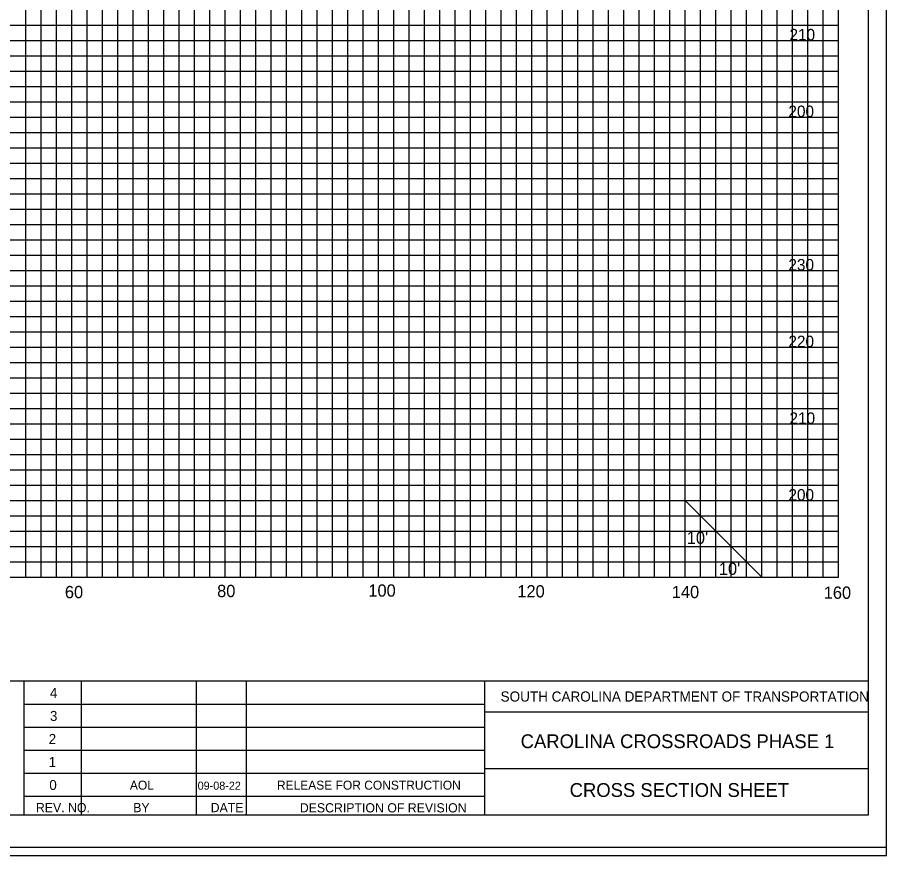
# Model space of a CAD drawing. Extents: x 967 to 1326, y 964 to 2304.
# Drawn here: x 1212.9 to 1326.3, y 963.7 to 1073 of the extents above; entities that cross this region are included whole.
import ezdxf

# ---------------------------------------------------------------- set-up
doc = ezdxf.new("R2010")
doc.units = 0
for name, color, linetype in [('Default', 7, 'Continuous'), ('RD_GPK_XS_Cell', 7, 'Continuous'), ('RD_PD_PaveShd', 7, 'Continuous'), ('RD_XS_ExGround', 7, 'Continuous'), ('RD_XS_ExPaveRet', 7, 'Continuous'), ('RD_XS_Misc_Line', 7, 'Continuous'), ('RD_XS_PaveOvlay', 7, 'Continuous'), ('RD_XS_TX_Elev_EX', 7, 'Continuous')]:
    doc.layers.add(name, color=color, linetype=linetype)

msp = doc.modelspace()

# ---------------------------------------------------------------- linework, layer by layer
at = {"layer": 'RD_GPK_XS_Cell'}
for p, q in [((1220, 1000), (1220, 1170)), ((1230, 1000), (1230, 1170)), ((1240, 1000), (1240, 1170)), ((1250, 1000), (1250, 1170)), ((1260, 1000), (1260, 1170)), ((1270, 1000), (1270, 1170)), ((1280, 1000), (1280, 1170)), ((1290, 1000), (1290, 1170)), ((1300, 1000), (1300, 1170)), ((1310, 1000), (1310, 1170)), ((1320, 1000), (1320, 1170)), ((1000, 1070), (1320, 1070)), ((1000, 1060), (1320, 1060)), ((1000, 1050), (1320, 1050)), ((1000, 1040), (1320, 1040)), ((1000, 1030), (1320, 1030)), ((1000, 1020), (1320, 1020)), ((1000, 1010), (1320, 1010)), ((1000, 1000), (1320, 1000))]:
    msp.add_line(p, q, dxfattribs=at)
at = {"layer": 'RD_PD_PaveShd'}
for p, q in [((1323.89, 1178.46), (1323.89, 968.98)), ((996.11, 986.49), (1323.89, 986.49)), ((1213.76, 968.94), (1213.76, 986.49)), ((1221.26, 968.95), (1221.26, 986.48)), ((1236.26, 968.95), (1236.26, 986.48)), ((1242.76, 968.95), (1242.76, 986.48)), ((1273.88, 968.98), (1273.88, 986.49)), ((1213.76, 983.48), (1273.88, 983.48)), ((1323.93, 982.43), (1273.88, 982.43)), ((1213.76, 980.48), (1273.88, 980.48)), ((1213.76, 977.48), (1273.88, 977.48)), ((1213.76, 974.48), (1273.88, 974.48)), ((1323.89, 975.04), (1273.88, 975.04)), ((1213.76, 971.48), (1273.88, 971.48)), ((1323.89, 968.98), (996.11, 968.98))]:
    msp.add_line(p, q, dxfattribs=at)
at = {"layer": 'RD_XS_ExGround'}
for p, q in [((1214, 1000), (1214, 1170)), ((1216, 1000), (1216, 1170)), ((1218, 1000), (1218, 1170)), ((1222, 1000), (1222, 1170)), ((1224, 1000), (1224, 1170)), ((1226, 1000), (1226, 1170)), ((1228, 1000), (1228, 1170)), ((1232, 1000), (1232, 1170)), ((1234, 1000), (1234, 1170)), ((1236, 1000), (1236, 1170)), ((1238, 1000), (1238, 1170)), ((1242, 1000), (1242, 1170)), ((1244, 1000), (1244, 1170)), ((1246, 1000), (1246, 1170)), ((1248, 1000), (1248, 1170)), ((1252, 1000), (1252, 1170)), ((1254, 1000), (1254, 1170)), ((1256, 1000), (1256, 1170)), ((1258, 1000), (1258, 1170)), ((1262, 1000), (1262, 1170)), ((1264, 1000), (1264, 1170)), ((1266, 1000), (1266, 1170)), ((1268, 1000), (1268, 1170)), ((1272, 1000), (1272, 1170)), ((1274, 1000), (1274, 1170)), ((1276, 1000), (1276, 1170)), ((1278, 1000), (1278, 1170)), ((1282, 1000), (1282, 1170)), ((1284, 1000), (1284, 1170)), ((1286, 1000), (1286, 1170)), ((1288, 1000), (1288, 1170)), ((1292, 1000), (1292, 1170)), ((1294, 1000), (1294, 1170)), ((1296, 1000), (1296, 1170)), ((1298, 1000), (1298, 1170)), ((1302, 1000), (1302, 1170)), ((1304, 1000), (1304, 1170)), ((1306, 1000), (1306, 1170)), ((1308, 1000), (1308, 1170)), ((1312, 1000), (1312, 1170)), ((1314, 1000), (1314, 1170)), ((1316, 1000), (1316, 1170)), ((1318, 1000), (1318, 1170)), ((1000, 1072), (1320, 1072)), ((1000, 1068), (1320, 1068)), ((1000, 1066), (1320, 1066)), ((1000, 1064), (1320, 1064)), ((1000, 1062), (1320, 1062)), ((1000, 1058), (1320, 1058)), ((1000, 1056), (1320, 1056)), ((1000, 1054), (1320, 1054)), ((1000, 1052), (1320, 1052)), ((1000, 1048), (1320, 1048)), ((1000, 1046), (1320, 1046)), ((1000, 1044), (1320, 1044)), ((1000, 1042), (1320, 1042)), ((1000, 1038), (1320, 1038)), ((1000, 1036), (1320, 1036)), ((1000, 1034), (1320, 1034)), ((1000, 1032), (1320, 1032)), ((1000, 1028), (1320, 1028)), ((1000, 1026), (1320, 1026)), ((1000, 1024), (1320, 1024)), ((1000, 1022), (1320, 1022)), ((1000, 1018), (1320, 1018)), ((1000, 1016), (1320, 1016)), ((1000, 1014), (1320, 1014)), ((1000, 1012), (1320, 1012)), ((1000, 1008), (1320, 1008)), ((1000, 1006), (1320, 1006)), ((1000, 1004), (1320, 1004)), ((1000, 1002), (1320, 1002))]:
    msp.add_line(p, q, dxfattribs=at)
at = {"layer": 'RD_XS_ExPaveRet'}
msp.add_line((1300, 1010), (1310, 1000), dxfattribs=at)
at = {"layer": 'RD_XS_PaveOvlay'}
msp.add_lwpolyline([(967.41, 963.72), (1326.28, 963.72), (1326.28, 1183.72), (967.41, 1183.72)], close=True, dxfattribs=at)
at = {"layer": 'RD_XS_TX_Elev_EX'}
for points in [[(967.41, 963.72), (1326.28, 963.72), (1326.28, 1183.72), (967.41, 1183.72)], [(988.52, 964.84), (1326.28, 964.84), (1326.28, 1182.6), (988.52, 1182.6)]]:
    msp.add_lwpolyline(points, close=True, dxfattribs=at)

# ---------------------------------------------------------------- texts
at = {"layer": 'Default'}
for s, p in [('210', (1313.61, 1070)), ('200', (1313.47, 1060)), ('230', (1313.47, 1040)), ('220', (1313.47, 1030)), ('210', (1313.61, 1020)), ('200', (1313.47, 1010))]:
    msp.add_text(s, height=1.5, dxfattribs=at).set_placement(p)
at = {"layer": 'RD_XS_ExPaveRet'}
for s, height, p in [("10'", 1.6, (1300.21, 1004.36)), ("10'", 1.6, (1304.4, 1000.32)), ('100', 1.6, (1258.67, 997.48)), ('60', 1.6, (1219.08, 997.28)), ('80', 1.6, (1238.94, 997.42)), ('120', 1.6, (1278.11, 997.38)), ('140', 1.6, (1298.26, 997.29)), ('160', 1.6, (1318.08, 997.2)), ('4', 1.3, (1217.13, 984.28)), ('SOUTH CAROLINA DEPARTMENT OF TRANSPORTATION', 1.32, (1275.92, 983.8)), ('3', 1.3, (1217.13, 981.28)), ('2', 1.3, (1216.97, 978.28)), ('1', 1.3, (1216.97, 975.28)), ('0', 1.3, (1217.05, 972.28)), ('REV. NO.', 1.2, (1215.3, 969.38)), ('BY', 1.2, (1227.99, 969.38)), ('DATE', 1.2, (1238.1, 969.38)), ('DESCRIPTION OF REVISION', 1.2, (1249.73, 969.35))]:
    msp.add_text(s, height=height, dxfattribs=at).set_placement(p)
for s, p in [('CAROLINA CROSSROADS PHASE 1', (1278.54, 977.73)), ('CROSS SECTION SHEET', (1284.93, 971.37))]:
    msp.add_text(s, height=1.8, rotation=0, dxfattribs=at).set_placement(p)
at = {"layer": 'RD_XS_Misc_Line'}
for s, height, p in [('AOL', 1.17, (1227.56, 972.32)), ('09-08-22', 1.053, (1236.4, 972.31)), ('RELEASE FOR CONSTRUCTION', 1.17, (1246.74, 972.32))]:
    msp.add_text(s, height=height, dxfattribs=at).set_placement(p)

doc.saveas('drawing.dxf')
